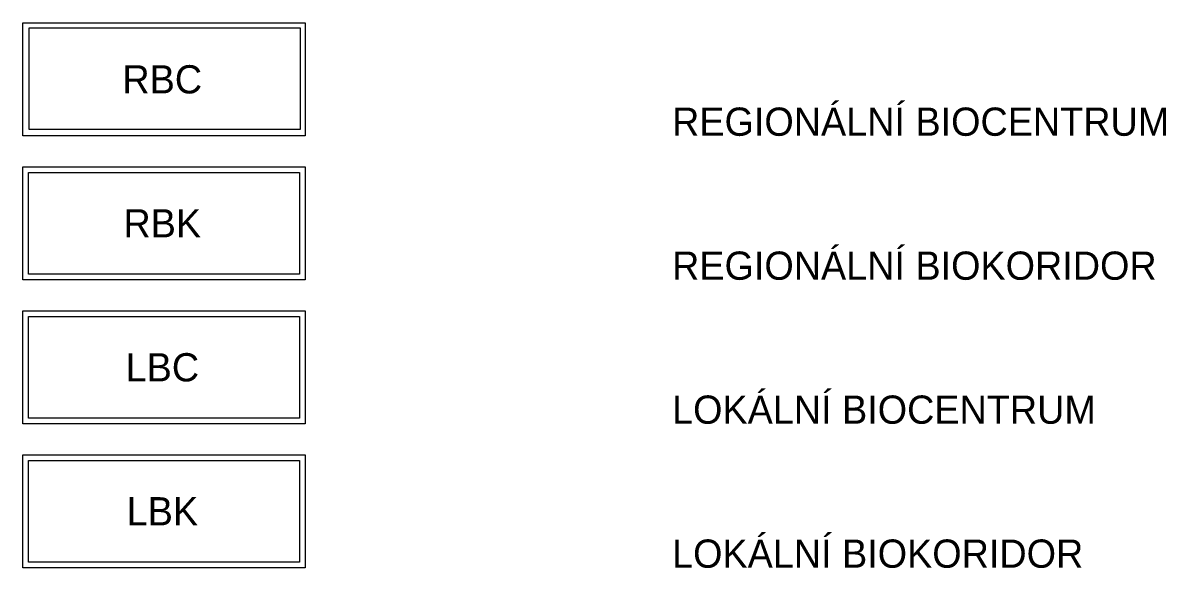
# Model space of a CAD drawing. Extents: x -450188 to -432919, y -1130252 to -1121189.
# Drawn here: x -433323.9 to -432919, y -1125088 to -1124894.8 of the extents above; entities that cross this region are included whole.
import ezdxf

# ---------------------------------------------------------------- set-up
doc = ezdxf.new("R2010")
doc.units = 0
for name, color, linetype in [('Vrstva 1', 7, 'Continuous'), ('Vrstva 30', 7, 'Continuous'), ('Vrstva 31', 7, 'Continuous'), ('Vrstva 32', 7, 'Continuous'), ('Vrstva 33', 7, 'Continuous'), ('Vrstva 36', 7, 'Continuous')]:
    doc.layers.add(name, color=color, linetype=linetype)

msp = doc.modelspace()

# ---------------------------------------------------------------- linework, layer by layer
at = {"layer": 'Vrstva 1'}
for points in [[(-433323.92, -1124894.81), (-433223.92, -1124894.81), (-433223.92, -1124934.81), (-433323.92, -1124934.81)], [(-433323.92, -1124945.81), (-433223.92, -1124945.81), (-433223.92, -1124985.81), (-433323.92, -1124985.81)], [(-433323.92, -1124996.81), (-433223.92, -1124996.81), (-433223.92, -1125036.81), (-433323.92, -1125036.81)], [(-433323.92, -1125047.81), (-433223.92, -1125047.81), (-433223.92, -1125087.81), (-433323.92, -1125087.81)]]:
    msp.add_lwpolyline(points, close=True, dxfattribs=at)
at = {"layer": 'Vrstva 30'}
msp.add_lwpolyline([(-433225.66, -1124932.55), (-433321.66, -1124932.55), (-433321.66, -1124896.55), (-433225.66, -1124896.55), (-433225.66, -1124932.55)], dxfattribs=at)
at = {"layer": 'Vrstva 31'}
msp.add_lwpolyline([(-433225.92, -1124983.81), (-433321.92, -1124983.81), (-433321.92, -1124947.81), (-433225.92, -1124947.81), (-433225.92, -1124983.81)], dxfattribs=at)
at = {"layer": 'Vrstva 32'}
msp.add_lwpolyline([(-433321.92, -1124998.81), (-433225.92, -1124998.81), (-433225.92, -1125034.81), (-433321.92, -1125034.81), (-433321.92, -1124998.81)], dxfattribs=at)
at = {"layer": 'Vrstva 33'}
msp.add_lwpolyline([(-433225.92, -1125085.81), (-433321.92, -1125085.81), (-433321.92, -1125049.81), (-433225.92, -1125049.81)], close=True, dxfattribs=at)

# ---------------------------------------------------------------- texts
at = {"layer": 'Vrstva 1'}
for s, p in [('REGIONÁLNÍ BIOCENTRUM', (-433093.97, -1124934.81)), ('REGIONÁLNÍ BIOKORIDOR', (-433093.97, -1124985.81)), ('LOKÁLNÍ BIOCENTRUM', (-433093.97, -1125036.81)), ('LOKÁLNÍ BIOKORIDOR', (-433093.97, -1125087.81))]:
    msp.add_text(s, height=10, dxfattribs=at).set_placement(p)
at = {"layer": 'Vrstva 36'}
for s, p in [('RBC', (-433288.67, -1124919.81)), ('RBK', (-433288.29, -1124970.81)), ('LBC', (-433287.51, -1125021.81)), ('LBK', (-433287.13, -1125072.81))]:
    msp.add_text(s, height=10, dxfattribs=at).set_placement(p)

doc.saveas('drawing.dxf')
